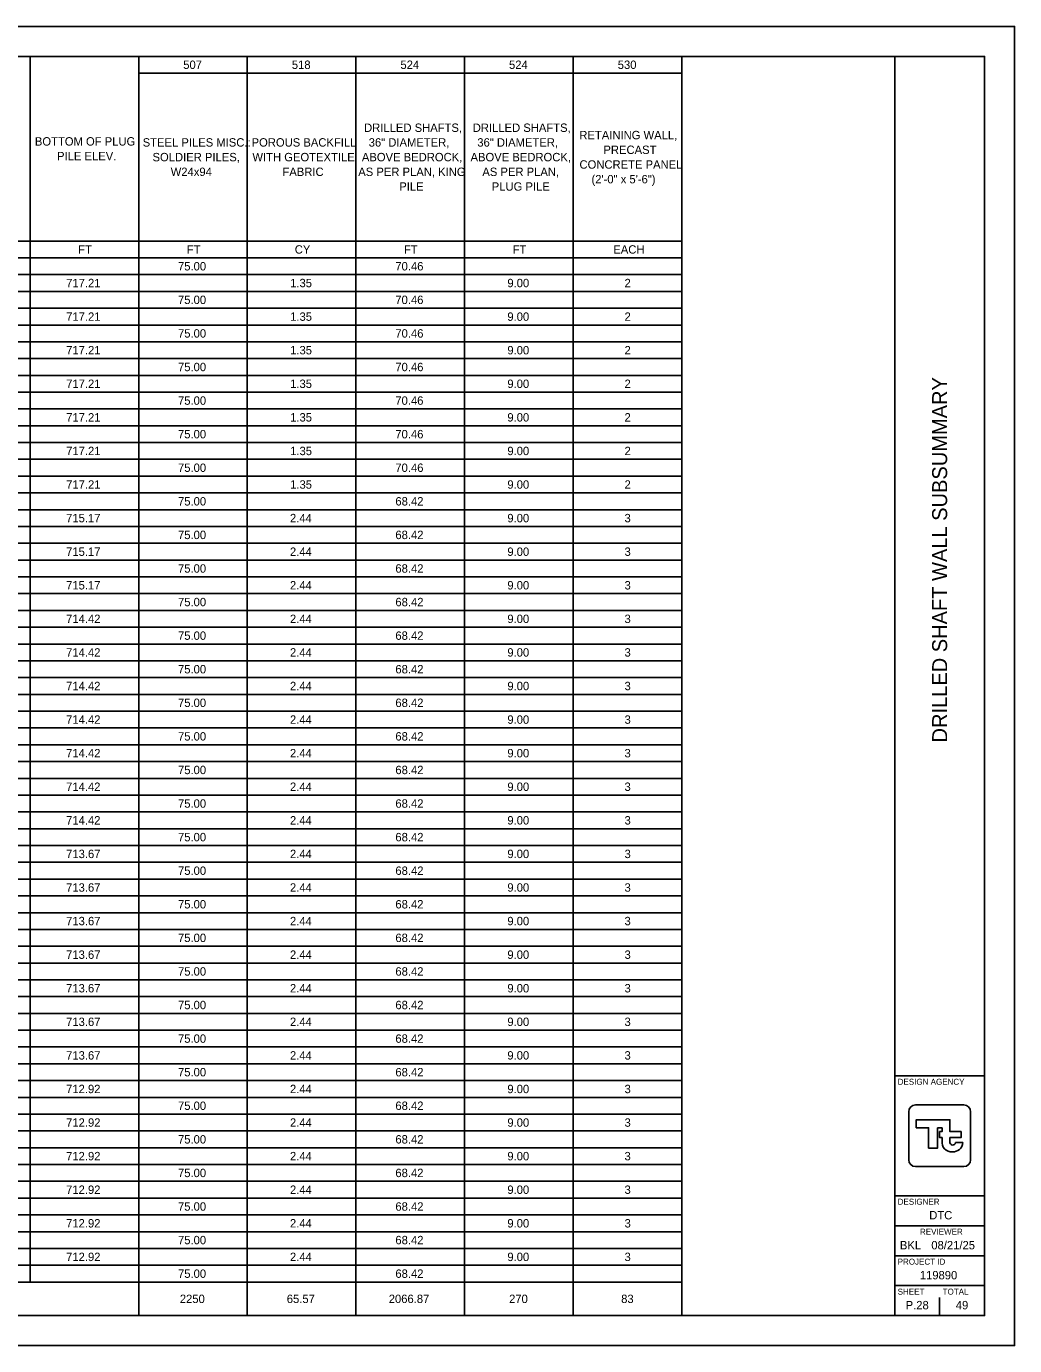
# Model space of a CAD drawing. Extents: x 0 to 34, y 0 to 22.
# Drawn here: x 17.52 to 34, y 0 to 22 of the extents above; entities that cross this region are included whole.
import ezdxf

# ---------------------------------------------------------------- set-up
doc = ezdxf.new("R2010")
doc.units = 0
for name, color, linetype in [('SH_Border', 7, 'Continuous'), ('SH_Cut_Line', 7, 'Continuous'), ('SH_Data', 7, 'Continuous'), ('SH_Text', 7, 'Continuous')]:
    doc.layers.add(name, color=color, linetype=linetype)

msp = doc.modelspace()

# ---------------------------------------------------------------- linework, layer by layer
at = {"layer": 'SH_Border'}
for p, q in [((32, 0.5), (32, 21.5)), ((32, 4.5), (33.5, 4.5)), ((32, 2.5), (33.5, 2.5)), ((32, 2), (33.5, 2)), ((32, 1.5), (33.5, 1.5)), ((32, 1), (33.5, 1))]:
    msp.add_line(p, q, dxfattribs=at)
msp.add_lwpolyline([(1.5, 21.5), (33.5, 21.5), (33.5, 0.5), (1.5, 0.5)], close=True, dxfattribs=at)
at = {"layer": 'SH_Cut_Line'}
msp.add_lwpolyline([(0, 0), (34, 0), (34, 22), (0, 22)], close=True, dxfattribs=at)
at = {"layer": 'SH_Data'}
for p, q in [((5.048, 21.5), (28.452, 21.5)), ((17.582, 21.5), (17.582, 1.06)), ((19.394, 21.5), (19.394, 0.5)), ((21.205, 21.5), (21.205, 0.5)), ((23.017, 21.5), (23.017, 0.5)), ((24.829, 21.5), (24.829, 0.5)), ((26.641, 21.5), (26.641, 0.5)), ((28.452, 21.5), (28.452, 0.5)), ((19.394, 21.22), (28.452, 21.22)), ((7.864, 18.42), (28.452, 18.42)), ((5.048, 18.14), (28.452, 18.14)), ((5.048, 17.86), (28.452, 17.86)), ((5.048, 17.58), (28.452, 17.58)), ((5.048, 17.3), (28.452, 17.3)), ((5.048, 17.02), (28.452, 17.02)), ((5.048, 16.74), (28.452, 16.74)), ((5.048, 16.46), (28.452, 16.46)), ((5.048, 16.18), (28.452, 16.18)), ((5.048, 15.9), (28.452, 15.9)), ((5.048, 15.62), (28.452, 15.62)), ((5.048, 15.34), (28.452, 15.34)), ((5.048, 15.06), (28.452, 15.06)), ((5.048, 14.78), (28.452, 14.78)), ((5.048, 14.5), (28.452, 14.5)), ((5.048, 14.22), (28.452, 14.22)), ((5.048, 13.94), (28.452, 13.94)), ((5.048, 13.66), (28.452, 13.66)), ((5.048, 13.38), (28.452, 13.38)), ((5.048, 13.1), (28.452, 13.1)), ((5.048, 12.82), (28.452, 12.82)), ((5.048, 12.54), (28.452, 12.54)), ((5.048, 12.26), (28.452, 12.26)), ((5.048, 11.98), (28.452, 11.98)), ((5.048, 11.7), (28.452, 11.7)), ((5.048, 11.42), (28.452, 11.42)), ((5.048, 11.14), (28.452, 11.14)), ((5.048, 10.86), (28.452, 10.86)), ((5.048, 10.58), (28.452, 10.58)), ((5.048, 10.3), (28.452, 10.3)), ((5.048, 10.02), (28.452, 10.02)), ((5.048, 9.74), (28.452, 9.74)), ((5.048, 9.46), (28.452, 9.46)), ((5.048, 9.18), (28.452, 9.18)), ((5.048, 8.9), (28.452, 8.9)), ((5.048, 8.62), (28.452, 8.62)), ((5.048, 8.34), (28.452, 8.34)), ((5.048, 8.06), (28.452, 8.06)), ((5.048, 7.78), (28.452, 7.78)), ((5.048, 7.5), (28.452, 7.5)), ((5.048, 7.22), (28.452, 7.22)), ((5.048, 6.94), (28.452, 6.94)), ((5.048, 6.66), (28.452, 6.66)), ((5.048, 6.38), (28.452, 6.38)), ((5.048, 6.1), (28.452, 6.1)), ((5.048, 5.82), (28.452, 5.82)), ((5.048, 5.54), (28.452, 5.54)), ((5.048, 5.26), (28.452, 5.26)), ((5.048, 4.98), (28.452, 4.98)), ((5.048, 4.7), (28.452, 4.7)), ((5.048, 4.42), (28.452, 4.42)), ((5.048, 4.14), (28.452, 4.14)), ((5.048, 3.86), (28.452, 3.86)), ((5.048, 3.58), (28.452, 3.58)), ((32.75, 3.5), (32.75, 3.5)), ((32.791, 3.415), (32.791, 3.415)), ((33.136, 3.385), (33.015, 3.385)), ((5.048, 3.3), (28.452, 3.3)), ((5.048, 3.02), (28.452, 3.02)), ((5.048, 2.74), (28.452, 2.74)), ((5.048, 2.46), (28.452, 2.46)), ((5.048, 2.18), (28.452, 2.18)), ((5.048, 1.9), (28.452, 1.9)), ((5.048, 1.62), (28.452, 1.62)), ((5.048, 1.34), (28.452, 1.34)), ((5.048, 1.06), (28.452, 1.06)), ((32.375, 0.675), (32.375, 0.675)), ((32.75, 0.5), (32.75, 0.8)), ((5.048, 0.5), (28.452, 0.5))]:
    msp.add_line(p, q, dxfattribs=at)
for points in [[(32.348, 4.014), (33.152, 4.014)], [(32.236, 3.099), (32.236, 3.901)], [(32.922, 3.399), (32.922, 3.47), (33.107, 3.47), (33.107, 3.568), (32.922, 3.568), (32.922, 3.768), (32.361, 3.768), (32.361, 3.632), (32.566, 3.632), (32.566, 3.294), (32.715, 3.294), (32.715, 3.63), (32.79, 3.63), (32.79, 3.568), (32.748, 3.568), (32.748, 3.47), (32.79, 3.47), (32.79, 3.415), (32.791, 3.415)], [(33.264, 3.901), (33.264, 3.099)], [(33.152, 2.986), (32.348, 2.986)]]:
    msp.add_lwpolyline(points, dxfattribs=at)
for centre, radius, start, end in [((32.348, 3.901), 0.113, 90, 180), ((33.152, 3.901), 0.113, 360, 90), ((32.949, 3.392), 0.16, 171.8856, 274.8323), ((32.968, 3.392), 0.0473, 171.8856, 350.9243), ((32.976, 3.392), 0.16, 265.1677, 357.3201), ((32.348, 3.099), 0.113, 180, 270), ((33.152, 3.099), 0.113, 270, 360)]:
    msp.add_arc(centre, radius, start, end, dxfattribs=at)

# ---------------------------------------------------------------- texts
msp.add_text('DRILLED SHAFT WALL SUBSUMMARY', height=0.25, rotation=90, dxfattribs=at).set_placement((32.875, 10.058))
for s, height, p in [('DESIGN AGENCY', 0.1, (32.05, 4.35)), ('DESIGNER', 0.1, (32.05, 2.35)), ('DTC', 0.14, (32.576, 2.105)), ('REVIEWER', 0.1, (32.422, 1.85)), ('BKL', 0.14, (32.087, 1.605)), ('08/21/25', 0.14, (32.611, 1.605)), ('PROJECT ID', 0.1, (32.05, 1.35)), ('119890', 0.14, (32.419, 1.105)), ('SHEET', 0.1, (32.05, 0.85)), ('TOTAL', 0.1, (32.8, 0.85)), ('P.28', 0.14, (32.183, 0.605)), ('49', 0.14, (33.019, 0.605))]:
    msp.add_text(s, height=height, dxfattribs=at).set_placement(p)
at = {"layer": 'SH_Text'}
for s, p in [('507', (20.136, 21.29)), ('518', (21.947, 21.29)), ('524', (23.758, 21.29)), ('524', (25.569, 21.29)), ('530', (27.382, 21.29)), ('DRILLED SHAFTS, ', (23.152, 20.24)), ('DRILLED SHAFTS, ', (24.964, 20.24)), ('RETAINING WALL, ', (26.741, 20.117)), ('BOTTOM OF PLUG ', (17.662, 20.012)), ('STEEL PILES MISC.: ', (19.46, 19.995)), ('POROUS BACKFILL ', (21.276, 19.995)), ('36" DIAMETER, ', (23.229, 19.995)), ('36" DIAMETER, ', (25.04, 19.995)), ('PILE ELEV.', (18.032, 19.767)), ('SOLDIER PILES, ', (19.624, 19.75)), ('WITH GEOTEXTILE ', (21.29, 19.75)), ('ABOVE BEDROCK, ', (23.115, 19.75)), ('ABOVE BEDROCK, ', (24.927, 19.75)), ('PRECAST ', (27.143, 19.872)), ('W24x94', (19.927, 19.505)), ('FABRIC', (21.791, 19.505)), ('AS PER PLAN, KING ', (23.055, 19.505)), ('AS PER PLAN, ', (25.124, 19.505)), ('CONCRETE PANEL ', (26.744, 19.627)), ('PILE', (23.739, 19.26)), ('PLUG PILE', (25.281, 19.26)), ('(2\'-0" x 5\'-6")', (26.944, 19.382)), ('FT', (18.383, 18.21)), ('FT', (20.195, 18.21)), ('CY', (21.996, 18.21)), ('FT', (23.818, 18.21)), ('FT', (25.63, 18.21)), ('EACH', (27.308, 18.21)), ('75.00', (20.049, 17.93)), ('70.46', (23.673, 17.93)), ('717.21', (18.184, 17.65)), ('1.35', (21.919, 17.65)), ('9.00', (25.541, 17.65)), ('2', (27.495, 17.65)), ('75.00', (20.049, 17.37)), ('70.46', (23.673, 17.37)), ('717.21', (18.184, 17.09)), ('1.35', (21.919, 17.09)), ('9.00', (25.541, 17.09)), ('2', (27.495, 17.09)), ('75.00', (20.049, 16.81)), ('70.46', (23.673, 16.81)), ('717.21', (18.184, 16.53)), ('1.35', (21.919, 16.53)), ('9.00', (25.541, 16.53)), ('2', (27.495, 16.53)), ('75.00', (20.049, 16.25)), ('70.46', (23.673, 16.25)), ('717.21', (18.184, 15.97)), ('1.35', (21.919, 15.97)), ('9.00', (25.541, 15.97)), ('2', (27.495, 15.97)), ('75.00', (20.049, 15.69)), ('70.46', (23.673, 15.69)), ('717.21', (18.184, 15.41)), ('1.35', (21.919, 15.41)), ('9.00', (25.541, 15.41)), ('2', (27.495, 15.41)), ('75.00', (20.049, 15.13)), ('70.46', (23.673, 15.13)), ('717.21', (18.184, 14.85)), ('1.35', (21.919, 14.85)), ('9.00', (25.541, 14.85)), ('2', (27.495, 14.85)), ('75.00', (20.049, 14.57)), ('70.46', (23.673, 14.57)), ('717.21', (18.184, 14.29)), ('1.35', (21.919, 14.29)), ('9.00', (25.541, 14.29)), ('2', (27.495, 14.29)), ('75.00', (20.049, 14.01)), ('68.42', (23.674, 14.01)), ('715.17', (18.183, 13.73)), ('2.44', (21.916, 13.73)), ('9.00', (25.541, 13.73)), ('3', (27.495, 13.73)), ('75.00', (20.049, 13.45)), ('68.42', (23.674, 13.45)), ('715.17', (18.183, 13.17)), ('2.44', (21.916, 13.17)), ('9.00', (25.541, 13.17)), ('3', (27.495, 13.17)), ('75.00', (20.049, 12.89)), ('68.42', (23.674, 12.89)), ('715.17', (18.183, 12.61)), ('2.44', (21.916, 12.61)), ('9.00', (25.541, 12.61)), ('3', (27.495, 12.61)), ('75.00', (20.049, 12.33)), ('68.42', (23.674, 12.33)), ('714.42', (18.183, 12.05)), ('2.44', (21.916, 12.05)), ('9.00', (25.541, 12.05)), ('3', (27.495, 12.05)), ('75.00', (20.049, 11.77)), ('68.42', (23.674, 11.77)), ('714.42', (18.183, 11.49)), ('2.44', (21.916, 11.49)), ('9.00', (25.541, 11.49)), ('3', (27.495, 11.49)), ('75.00', (20.049, 11.21)), ('68.42', (23.674, 11.21)), ('714.42', (18.183, 10.93)), ('2.44', (21.916, 10.93)), ('9.00', (25.541, 10.93)), ('3', (27.495, 10.93)), ('75.00', (20.049, 10.65)), ('68.42', (23.674, 10.65)), ('714.42', (18.183, 10.37)), ('2.44', (21.916, 10.37)), ('9.00', (25.541, 10.37)), ('3', (27.495, 10.37)), ('75.00', (20.049, 10.09)), ('68.42', (23.674, 10.09)), ('714.42', (18.183, 9.81)), ('2.44', (21.916, 9.81)), ('9.00', (25.541, 9.81)), ('3', (27.495, 9.81)), ('75.00', (20.049, 9.53)), ('68.42', (23.674, 9.53)), ('714.42', (18.183, 9.25)), ('2.44', (21.916, 9.25)), ('9.00', (25.541, 9.25)), ('3', (27.495, 9.25)), ('75.00', (20.049, 8.97)), ('68.42', (23.674, 8.97)), ('714.42', (18.183, 8.69)), ('2.44', (21.916, 8.69)), ('9.00', (25.541, 8.69)), ('3', (27.495, 8.69)), ('75.00', (20.049, 8.41)), ('68.42', (23.674, 8.41)), ('713.67', (18.183, 8.13)), ('2.44', (21.916, 8.13)), ('9.00', (25.541, 8.13)), ('3', (27.495, 8.13)), ('75.00', (20.049, 7.85)), ('68.42', (23.674, 7.85)), ('713.67', (18.183, 7.57)), ('2.44', (21.916, 7.57)), ('9.00', (25.541, 7.57)), ('3', (27.495, 7.57)), ('75.00', (20.049, 7.29)), ('68.42', (23.674, 7.29)), ('713.67', (18.183, 7.01)), ('2.44', (21.916, 7.01)), ('9.00', (25.541, 7.01)), ('3', (27.495, 7.01)), ('75.00', (20.049, 6.73)), ('68.42', (23.674, 6.73)), ('713.67', (18.183, 6.45)), ('2.44', (21.916, 6.45)), ('9.00', (25.541, 6.45)), ('3', (27.495, 6.45)), ('75.00', (20.049, 6.17)), ('68.42', (23.674, 6.17)), ('713.67', (18.183, 5.89)), ('2.44', (21.916, 5.89)), ('9.00', (25.541, 5.89)), ('3', (27.495, 5.89)), ('75.00', (20.049, 5.61)), ('68.42', (23.674, 5.61)), ('713.67', (18.183, 5.33)), ('2.44', (21.916, 5.33)), ('9.00', (25.541, 5.33)), ('3', (27.495, 5.33)), ('75.00', (20.049, 5.05)), ('68.42', (23.674, 5.05)), ('713.67', (18.183, 4.77)), ('2.44', (21.916, 4.77)), ('9.00', (25.541, 4.77)), ('3', (27.495, 4.77)), ('75.00', (20.049, 4.49)), ('68.42', (23.674, 4.49)), ('712.92', (18.183, 4.21)), ('2.44', (21.916, 4.21)), ('9.00', (25.541, 4.21)), ('3', (27.495, 4.21)), ('75.00', (20.049, 3.93)), ('68.42', (23.674, 3.93)), ('712.92', (18.183, 3.65)), ('2.44', (21.916, 3.65)), ('9.00', (25.541, 3.65)), ('3', (27.495, 3.65)), ('75.00', (20.049, 3.37)), ('68.42', (23.674, 3.37)), ('712.92', (18.183, 3.09)), ('2.44', (21.916, 3.09)), ('9.00', (25.541, 3.09)), ('3', (27.495, 3.09)), ('75.00', (20.049, 2.81)), ('68.42', (23.674, 2.81)), ('712.92', (18.183, 2.53)), ('2.44', (21.916, 2.53)), ('9.00', (25.541, 2.53)), ('3', (27.495, 2.53)), ('75.00', (20.049, 2.25)), ('68.42', (23.674, 2.25)), ('712.92', (18.183, 1.97)), ('2.44', (21.916, 1.97)), ('9.00', (25.541, 1.97)), ('3', (27.495, 1.97)), ('75.00', (20.049, 1.69)), ('68.42', (23.674, 1.69)), ('712.92', (18.183, 1.41)), ('2.44', (21.916, 1.41)), ('9.00', (25.541, 1.41)), ('3', (27.495, 1.41)), ('75.00', (20.049, 1.13)), ('68.42', (23.674, 1.13)), ('2250', (20.079, 0.71)), ('65.57', (21.863, 0.71)), ('2066.87', (23.563, 0.71)), ('270', (25.57, 0.71)), ('83', (27.439, 0.71))]:
    msp.add_text(s, height=0.14, dxfattribs=at).set_placement(p)

doc.saveas('drawing.dxf')
